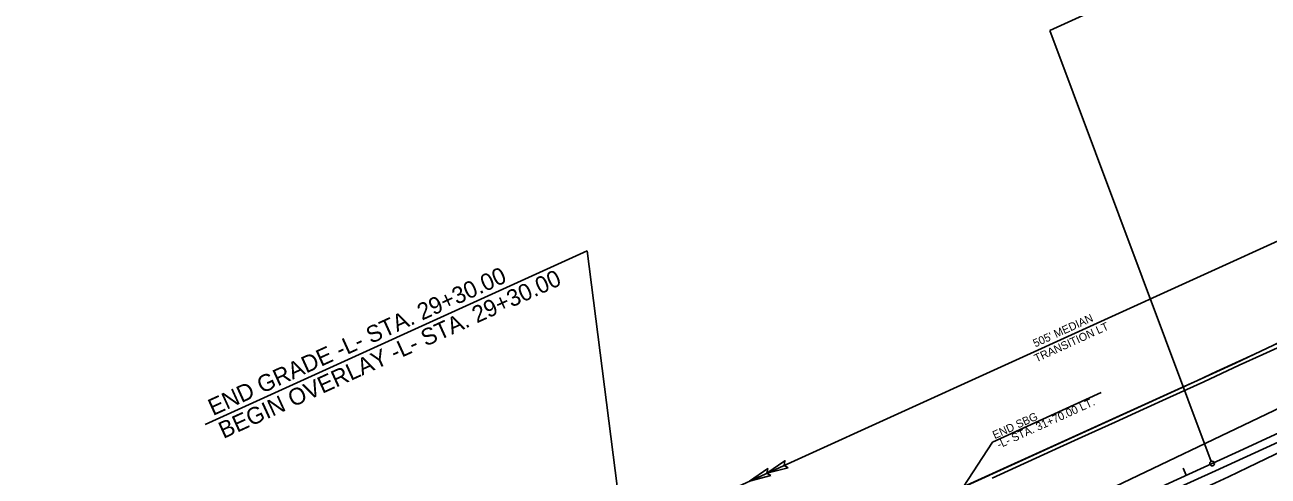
# Model space of a CAD drawing. Extents: x 2242984 to 2250974, y 661492 to 664681.
# Drawn here: x 2249051 to 2249828, y 663738 to 664020 of the extents above; entities that cross this region are included whole.
import ezdxf

# ---------------------------------------------------------------- set-up
doc = ezdxf.new("R2010")
doc.units = 0
for name, color, linetype in [('Prop Dimension', 7, 'Continuous'), ('Prop Dimension Text', 7, 'Continuous'), ('Prop DSN Text', 7, 'Continuous'), ('Prop Guardrail', 7, 'Continuous'), ('Prop Guardrail Double Faced', 7, 'Continuous'), ('Prop Horizontal Alignment', 7, 'Continuous'), ('Prop Horizontal Alignment Station Label', 7, 'Continuous'), ('Prop Horizontal Alignment Tick Small', 7, 'Continuous'), ('Prop Paved Shoulder', 7, 'Continuous'), ('Prop Terminator CELL', 7, 'Continuous'), ('Scratch_Level_6', 7, 'Continuous')]:
    doc.layers.add(name, color=color, linetype=linetype)

msp = doc.modelspace()

# ---------------------------------------------------------------- linework, layer by layer
at = {"layer": 'Prop Dimension'}
for p, q in [((2249394.77, 663685.73), (2249854.28, 663894.46)), ((2249402.54, 663879.15), (2249163.91, 663770.72)), ((2249440.09, 663585.95), (2249402.54, 663879.15))]:
    msp.add_line(p, q, dxfattribs=at)
at = {"layer": 'Prop DSN Text'}
for p, q in [((2249723.79, 663790.69), (2249655.93, 663759.77)), ((2249655.93, 663759.77), (2249637.51, 663731.64))]:
    msp.add_line(p, q, dxfattribs=at)
at = {"layer": 'Prop Guardrail'}
msp.add_line((2249771.98, 663792.73), (2249637.51, 663731.64), dxfattribs=at)
for radius, start, end in [(5678.58, 294.43013, 298.65426), (5778.08, 294.430126, 298.67506)]:
    msp.add_arc((2247423.42, 668962.88), radius, start, end, dxfattribs=at)
at = {"layer": 'Prop Guardrail Double Faced'}
msp.add_line((2249770.84, 663730.7), (2249795.14, 663741.74), dxfattribs=at)
msp.add_arc((2247423.42, 668962.88), 5734.58, 294.430126, 298.75316, dxfattribs=at)
at = {"layer": 'Prop Horizontal Alignment'}
msp.add_line((2247500.8, 662705.02), (2249793.08, 663746.29), dxfattribs=at)
msp.add_arc((2247423.42, 668962.88), 5729.58, 294.43013, 308.28013, dxfattribs=at)
at = {"layer": 'Prop Horizontal Alignment Station Label'}
for p, q in [((2249691.57, 664016.65), (2249801.59, 664066.79)), ((2249792.55, 663747.7), (2249691.57, 664016.65))]:
    msp.add_line(p, q, dxfattribs=at)
msp.add_circle((2249793.08, 663746.29), 1.5, dxfattribs=at)
at = {"layer": 'Prop Horizontal Alignment Tick Small'}
msp.add_line((2249776.96, 663738.97), (2249774.9, 663743.53), dxfattribs=at)
at = {"layer": 'Prop Paved Shoulder'}
msp.add_line((2249437.63, 663591.42), (2249853.74, 663789.97), dxfattribs=at)
for points in [[(2250163.18, 663918.53), (2250141.76, 663907.17), (2250123.19, 663897.33), (2250103.59, 663886.75), (2250085.93, 663877.2), (2250066.71, 663867.19), (2250050.24, 663858.7), (2250033.81, 663851.08), (2250013.9, 663840.08), (2249997.54, 663832.27), (2249982.72, 663824.86), (2249962.36, 663814.71), (2249947.05, 663807.05), (2249930.38, 663798.85), (2249911.87, 663789.95), (2249894.79, 663781.72), (2249875.22, 663772.32), (2249857.01, 663763.64), (2249837.93, 663754.68), (2249815.49, 663743.88), (2249803.29, 663738.06), (2249784.26, 663729.26), (2249767.73, 663721.96), (2249763, 663719.65)], [(2249843.45, 663822.95), (2249824.73, 663814.35), (2249810.06, 663807.67), (2249787.9, 663797.34), (2249766.72, 663787.83), (2249750.29, 663780.29), (2249732.43, 663772.23), (2249711.61, 663762.73), (2249697.93, 663756.48), (2249655.6, 663737.28)]]:
    msp.add_lwpolyline(points, dxfattribs=at)
at = {"layer": 'Prop Terminator CELL'}
for points in [[(2249517.28, 663738.82), (2249504.02, 663735.36), (2249515.39, 663743.16), (2249514.81, 663740.26)], [(2249528.06, 663743.72), (2249514.8, 663740.25), (2249526.17, 663748.05), (2249525.59, 663745.16)]]:
    msp.add_lwpolyline(points, close=True, dxfattribs=at)
at = {"layer": 'Scratch_Level_6'}
msp.add_line((2249637.47, 663731.73), (2249771.94, 663792.82), dxfattribs=at)
for radius, start, end in [(5678.48, 294.43013, 298.65426), (5778.18, 294.430126, 298.67506)]:
    msp.add_arc((2247423.42, 668962.88), radius, start, end, dxfattribs=at)

# ---------------------------------------------------------------- texts
at = {"layer": 'Prop Dimension'}
for s, height, rotation, p in [('END GRADE -L- STA. 29+30.00', 10.5, 24.49794, (2249168.75, 663775.95)), ('BEGIN OVERLAY -L- STA. 29+30.00', 10.5, 24.49794, (2249175.28, 663761.62)), ("505' MEDIAN", 5, 24.43013, (2249682.56, 663818.78))]:
    msp.add_text(s, height=height, rotation=rotation, dxfattribs=at).set_placement(p)
at = {"layer": 'Prop Dimension Text'}
msp.add_text('TRANSITION LT', height=5, rotation=24.49794, dxfattribs=at).set_placement((2249683.33, 663809.43))
at = {"layer": 'Prop DSN Text'}
for s, p in [('-L- STA. 31+70.00 LT.', (2249659.99, 663755.56)), ('END SBG', (2249657.27, 663761.52))]:
    msp.add_text(s, height=5, rotation=24.49794, dxfattribs=at).set_placement(p)

doc.saveas('drawing.dxf')
